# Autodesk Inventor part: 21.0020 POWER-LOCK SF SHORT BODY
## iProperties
Created: 2012-06
Part Number: 21.0020 POWER-LOCK SF SHORT BODY
Document SubType Name: Modeling
Designer: Administrator
Density: 7.85 g/cm^3
Material: Steel
Mass: 10.6604 g
Surface Area: 14.0902 cm^2
Volume: 1.35801 cm^3
Author: Administrator
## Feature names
1. Base1
2. Extrusion1
3. Hole2
